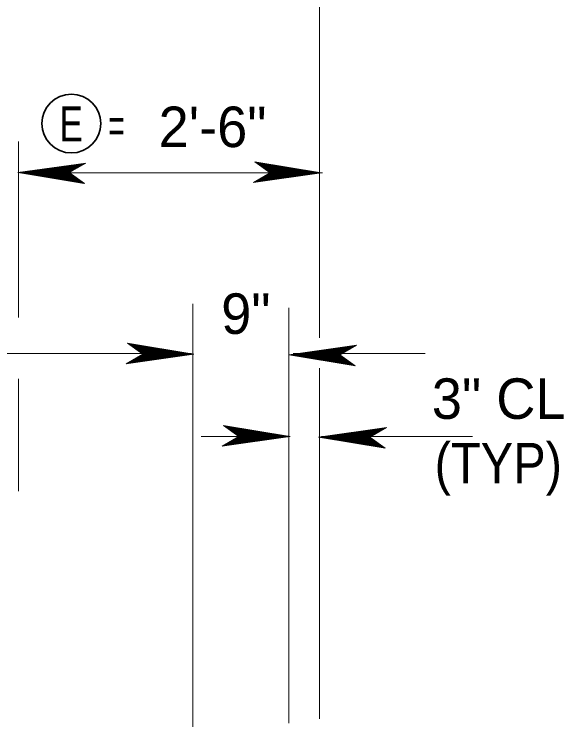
# Model space of a CAD drawing. Extents: x 144 to 252, y 360 to 425.
# Drawn here: x 195.35 to 199.8, y 394.5 to 400.27 of the extents above; entities that cross this region are included whole.
import ezdxf
from ezdxf.enums import TextEntityAlignment as Align

# ---------------------------------------------------------------- set-up
doc = ezdxf.new("R2010")
doc.units = 0
doc.header["$LTSCALE"] = 0.13
for name, color, linetype, lineweight in [('1', 7, 'Continuous', 40), ('16', 7, 'Continuous', 13), ('3', 7, 'Continuous', 13)]:
    doc.layers.add(name, color=color, linetype=linetype, lineweight=lineweight)

msp = doc.modelspace()

# ---------------------------------------------------------------- linework, layer by layer
at = {"layer": '1', "lineweight": 35}
msp.add_circle((195.8129, 399.3848), 0.238, dxfattribs=at)
at = {"layer": '3'}
for p, q in [((197.8208, 397.6492), (197.8208, 401.0623)), ((197.8208, 397.7177), (197.8208, 400.0347)), ((195.3853, 397.8149), (195.3853, 399.2386)), ((195.9291, 399.065), (195.3803, 398.9872)), ((195.9231, 399.0615), (195.3947, 398.9866)), ((195.9196, 399.0595), (195.4056, 398.9866)), ((195.7955, 398.9871), (195.9291, 399.065)), ((197.8364, 398.9853), (197.2987, 399.0746)), ((197.2987, 399.0746), (197.4212, 398.9855)), ((197.822, 398.986), (197.302, 399.0722)), ((197.8112, 398.986), (197.3053, 399.0699)), ((197.7968, 398.986), (197.3095, 399.0668)), ((197.784, 398.986), (197.3132, 399.0641)), ((197.7727, 398.986), (197.3166, 399.0617)), ((197.7583, 398.986), (197.3208, 399.0585)), ((195.915, 399.0568), (195.42, 398.9866)), ((195.9109, 399.0544), (195.4327, 398.9866)), ((195.9109, 399.0544), (195.4327, 398.9866)), ((195.9073, 399.0523), (195.4441, 398.9866)), ((195.9027, 399.0496), (195.4585, 398.9866)), ((195.8986, 399.0472), (195.4712, 398.9866)), ((195.8942, 399.0447), (195.485, 398.9866)), ((195.8897, 399.0421), (195.4988, 398.9866)), ((195.8855, 399.0396), (195.5121, 398.9866)), ((195.881, 399.0369), (195.526, 398.9866)), ((195.877, 399.0347), (195.5386, 398.9866)), ((195.8732, 399.0324), (195.55, 398.9866)), ((195.8682, 399.0296), (195.5657, 398.9866)), ((195.8638, 399.0269), (195.5795, 398.9866)), ((195.8567, 399.0227), (195.5975, 398.9861)), ((195.8598, 399.0247), (195.5991, 398.9877)), ((195.8522, 399.0202), (195.6114, 398.9861)), ((195.848, 399.0177), (195.6246, 398.9861)), ((195.8465, 399.0168), (195.6337, 398.9866)), ((195.8426, 399.0146), (195.6457, 398.9866)), ((195.8382, 399.0119), (195.6595, 398.9866)), ((195.8332, 399.0091), (195.6752, 398.9866)), ((195.8291, 399.0067), (195.6877, 398.9866)), ((195.8248, 399.0042), (195.701, 398.9866)), ((195.821, 399.0019), (195.713, 398.9866)), ((197.7455, 398.986), (197.3246, 399.0557)), ((197.7318, 398.986), (197.3287, 399.0528)), ((197.7179, 398.986), (197.3328, 399.0498)), ((197.7047, 398.986), (197.3367, 399.047)), ((197.6907, 398.986), (197.3407, 399.044)), ((197.6782, 398.986), (197.3445, 399.0413)), ((197.6668, 398.986), (197.3479, 399.0388)), ((197.6511, 398.986), (197.3525, 399.0355)), ((197.6372, 398.986), (197.3566, 399.0325)), ((197.6192, 398.9865), (197.3608, 399.0294)), ((197.6053, 398.9865), (197.365, 399.0264)), ((197.5922, 398.9865), (197.3688, 399.0236)), ((197.5831, 398.986), (197.3726, 399.0208)), ((197.5711, 398.986), (197.3762, 399.0182)), ((197.5572, 398.986), (197.3802, 399.0152)), ((197.5416, 398.986), (197.3849, 399.012)), ((197.529, 398.986), (197.3886, 399.0093)), ((197.5157, 398.986), (197.3925, 399.0064)), ((197.5037, 398.986), (197.3961, 399.0037)), ((197.4892, 398.986), (197.4003, 399.0007)), ((195.3803, 398.9872), (195.918, 398.898)), ((195.7957, 398.9872), (195.3803, 398.9872)), ((195.3947, 398.9866), (195.9147, 398.9003)), ((195.4056, 398.9866), (195.9115, 398.9027)), ((197.8445, 398.9853), (195.4169, 398.9853)), ((195.42, 398.9866), (195.9073, 398.9058)), ((195.4327, 398.9866), (195.9035, 398.9085)), ((195.4441, 398.9866), (195.9002, 398.9109)), ((195.4585, 398.9866), (195.8959, 398.9141)), ((195.4712, 398.9866), (195.8922, 398.9168)), ((195.485, 398.9866), (195.8881, 398.9197)), ((195.4988, 398.9866), (195.884, 398.9228)), ((195.5121, 398.9866), (195.8801, 398.9256)), ((195.526, 398.9866), (195.876, 398.9286)), ((195.5386, 398.9866), (195.8722, 398.9312)), ((195.55, 398.9866), (195.8688, 398.9337)), ((195.5657, 398.9866), (195.8642, 398.9371)), ((195.5795, 398.9866), (195.8602, 398.9401)), ((195.5975, 398.9861), (195.8559, 398.9432)), ((195.6114, 398.9861), (195.8517, 398.9462)), ((195.6246, 398.9861), (195.8479, 398.949)), ((195.6337, 398.9866), (195.8442, 398.9518)), ((195.6457, 398.9866), (195.8406, 398.9543)), ((195.6595, 398.9866), (195.8365, 398.9573)), ((195.6752, 398.9866), (195.8318, 398.9606)), ((195.6877, 398.9866), (195.8282, 398.9633)), ((195.701, 398.9866), (195.8243, 398.9662)), ((195.713, 398.9866), (195.8207, 398.9688)), ((195.8163, 398.9992), (195.7275, 398.9866)), ((195.7275, 398.9866), (195.8164, 398.9718)), ((195.8119, 398.9967), (195.7413, 398.9866)), ((195.7413, 398.9866), (195.8123, 398.9748)), ((195.8078, 398.9943), (195.754, 398.9866)), ((195.754, 398.9866), (195.8086, 398.9776)), ((195.7672, 398.9866), (195.8047, 398.9804)), ((195.8026, 398.9912), (195.7775, 398.9877)), ((195.7999, 398.9897), (195.7787, 398.9866)), ((195.7787, 398.9866), (195.8012, 398.9828)), ((195.7888, 398.9866), (195.7982, 398.9851)), ((195.918, 398.898), (195.7955, 398.9871)), ((197.4212, 398.9855), (197.2877, 398.9076)), ((197.2877, 398.9076), (197.8364, 398.9853)), ((197.2937, 398.9111), (197.822, 398.986)), ((197.2972, 398.9131), (197.8112, 398.986)), ((197.3017, 398.9158), (197.7968, 398.986)), ((197.3058, 398.9182), (197.784, 398.986)), ((197.3058, 398.9182), (197.784, 398.986)), ((197.3095, 398.9203), (197.7727, 398.986)), ((197.3141, 398.923), (197.7583, 398.986)), ((197.3182, 398.9254), (197.7455, 398.986)), ((197.3226, 398.9279), (197.7318, 398.986)), ((197.327, 398.9305), (197.7179, 398.986)), ((197.3312, 398.933), (197.7047, 398.986)), ((197.3357, 398.9357), (197.6907, 398.986)), ((197.3397, 398.9379), (197.6782, 398.986)), ((197.3435, 398.9402), (197.6668, 398.986)), ((197.3485, 398.943), (197.6511, 398.986)), ((197.3529, 398.9457), (197.6372, 398.986)), ((197.3569, 398.9479), (197.6177, 398.9849)), ((197.3601, 398.9498), (197.6192, 398.9865)), ((197.3645, 398.9524), (197.6053, 398.9865)), ((197.3688, 398.9549), (197.5922, 398.9865)), ((197.3702, 398.9557), (197.5831, 398.986)), ((197.3742, 398.958), (197.5711, 398.986)), ((197.3786, 398.9607), (197.5572, 398.986)), ((197.3836, 398.9635), (197.5416, 398.986)), ((197.3877, 398.9659), (197.529, 398.986)), ((197.3919, 398.9684), (197.5157, 398.986)), ((197.3957, 398.9707), (197.5037, 398.986)), ((197.4004, 398.9733), (197.4892, 398.986)), ((197.4754, 398.986), (197.4045, 398.9977)), ((197.4048, 398.9759), (197.4754, 398.986)), ((197.4627, 398.986), (197.4082, 398.995)), ((197.4089, 398.9783), (197.4627, 398.986)), ((197.4495, 398.986), (197.4121, 398.9922)), ((197.4142, 398.9813), (197.4392, 398.9849)), ((197.4381, 398.986), (197.4155, 398.9898)), ((197.4168, 398.9829), (197.4381, 398.986)), ((197.4279, 398.986), (197.4185, 398.9875)), ((197.421, 398.9853), (197.8364, 398.9853)), ((196.7952, 394.4992), (196.7952, 397.9255)), ((197.5733, 394.5272), (197.5733, 397.8934)), ((196.8055, 397.5167), (196.2678, 397.6059)), ((196.2678, 397.6059), (196.3903, 397.5168)), ((196.7911, 397.5173), (196.2711, 397.6036)), ((196.7802, 397.5173), (196.2743, 397.6012)), ((196.7658, 397.5173), (196.2786, 397.5981)), ((196.7531, 397.5173), (196.2823, 397.5954)), ((196.7417, 397.5173), (196.2857, 397.593)), ((196.7273, 397.5173), (196.2899, 397.5898)), ((196.7146, 397.5173), (196.2937, 397.5871)), ((196.7008, 397.5173), (196.2977, 397.5842)), ((196.687, 397.5173), (196.3018, 397.5812)), ((196.6737, 397.5173), (196.3057, 397.5783)), ((196.6598, 397.5173), (196.3098, 397.5753)), ((196.6472, 397.5173), (196.3136, 397.5727)), ((196.6358, 397.5173), (196.317, 397.5702)), ((196.6202, 397.5173), (196.3216, 397.5668)), ((196.6063, 397.5173), (196.3257, 397.5638)), ((196.5883, 397.5178), (196.3299, 397.5607)), ((196.5744, 397.5178), (196.3341, 397.5577)), ((198.1208, 397.5888), (197.5721, 397.511)), ((198.1148, 397.5852), (197.5865, 397.5103)), ((198.1113, 397.5832), (197.5973, 397.5103)), ((198.1068, 397.5806), (197.6118, 397.5103)), ((198.1027, 397.5782), (197.6245, 397.5103)), ((198.1027, 397.5782), (197.6245, 397.5103)), ((198.099, 397.576), (197.6358, 397.5103)), ((198.0944, 397.5733), (197.6502, 397.5103)), ((198.0903, 397.5709), (197.663, 397.5103)), ((198.0859, 397.5684), (197.6767, 397.5103)), ((198.0815, 397.5658), (197.6906, 397.5103)), ((198.0772, 397.5633), (197.7038, 397.5103)), ((198.0727, 397.5607), (197.7177, 397.5103)), ((198.0687, 397.5584), (197.7303, 397.5103)), ((197.9872, 397.5108), (198.1208, 397.5888)), ((190.8138, 397.5218), (196.7735, 397.5218)), ((190.8303, 397.5218), (196.7835, 397.5218)), ((196.3903, 397.5168), (196.2567, 397.4389)), ((196.2567, 397.4389), (196.8055, 397.5167)), ((196.2627, 397.4424), (196.7911, 397.5173)), ((196.2662, 397.4444), (196.7802, 397.5173)), ((196.2708, 397.4471), (196.7658, 397.5173)), ((196.2749, 397.4495), (196.7531, 397.5173)), ((196.2749, 397.4495), (196.7531, 397.5173)), ((196.2786, 397.4517), (196.7417, 397.5173)), ((196.2832, 397.4543), (196.7273, 397.5173)), ((196.2873, 397.4567), (196.7146, 397.5173)), ((196.2917, 397.4592), (196.7008, 397.5173)), ((196.2961, 397.4618), (196.687, 397.5173)), ((196.3003, 397.4643), (196.6737, 397.5173)), ((196.3048, 397.467), (196.6598, 397.5173)), ((196.3088, 397.4692), (196.6472, 397.5173)), ((196.3126, 397.4715), (196.6358, 397.5173)), ((196.3176, 397.4743), (196.6202, 397.5173)), ((196.322, 397.477), (196.6063, 397.5173)), ((196.326, 397.4792), (196.5867, 397.5163)), ((196.3292, 397.4812), (196.5883, 397.5178)), ((196.3336, 397.4837), (196.5744, 397.5178)), ((196.3378, 397.4862), (196.5613, 397.5178)), ((196.5613, 397.5178), (196.3379, 397.5549)), ((196.3393, 397.4871), (196.5522, 397.5173)), ((196.5522, 397.5173), (196.3417, 397.5522)), ((196.3432, 397.4893), (196.5402, 397.5173)), ((196.5402, 397.5173), (196.3452, 397.5496)), ((196.3477, 397.492), (196.5263, 397.5173)), ((196.5263, 397.5173), (196.3493, 397.5466)), ((196.3527, 397.4948), (196.5107, 397.5173)), ((196.5107, 397.5173), (196.354, 397.5433)), ((196.3568, 397.4973), (196.4981, 397.5173)), ((196.4981, 397.5173), (196.3577, 397.5406)), ((196.361, 397.4998), (196.4848, 397.5173)), ((196.4848, 397.5173), (196.3616, 397.5377)), ((196.3648, 397.502), (196.4728, 397.5173)), ((196.4728, 397.5173), (196.3652, 397.5351)), ((196.4583, 397.5173), (196.3694, 397.5321)), ((196.3695, 397.5047), (196.4583, 397.5173)), ((196.4445, 397.5173), (196.3736, 397.5291)), ((196.3739, 397.5072), (196.4445, 397.5173)), ((196.4318, 397.5173), (196.3773, 397.5263)), ((196.378, 397.5096), (196.4318, 397.5173)), ((196.4186, 397.5173), (196.3812, 397.5235)), ((196.3833, 397.5127), (196.4083, 397.5163)), ((196.4072, 397.5173), (196.3846, 397.5211)), ((196.3859, 397.5143), (196.4072, 397.5173)), ((196.397, 397.5173), (196.3876, 397.5188)), ((196.3901, 397.5167), (196.8055, 397.5167)), ((197.5721, 397.511), (198.1097, 397.4217)), ((197.9875, 397.511), (197.5721, 397.511)), ((197.5865, 397.5103), (198.1065, 397.4241)), ((197.5973, 397.5103), (198.1033, 397.4264)), ((197.6077, 397.5218), (198.6776, 397.5218)), ((197.6118, 397.5103), (198.099, 397.4296)), ((197.6245, 397.5103), (198.0952, 397.4323)), ((197.6358, 397.5103), (198.0919, 397.4347)), ((197.6502, 397.5103), (198.0877, 397.4378)), ((197.663, 397.5103), (198.0839, 397.4406)), ((197.6767, 397.5103), (198.0798, 397.4435)), ((197.6906, 397.5103), (198.0757, 397.4465)), ((197.7038, 397.5103), (198.0718, 397.4493)), ((197.7177, 397.5103), (198.0677, 397.4523)), ((197.7303, 397.5103), (198.064, 397.455)), ((198.065, 397.5562), (197.7417, 397.5103)), ((197.7417, 397.5103), (198.0606, 397.4575)), ((198.06, 397.5533), (197.7574, 397.5103)), ((197.7574, 397.5103), (198.056, 397.4608)), ((198.0556, 397.5507), (197.7712, 397.5103)), ((197.7712, 397.5103), (198.0519, 397.4638)), ((198.0484, 397.5465), (197.7892, 397.5098)), ((197.7892, 397.5098), (198.0477, 397.4669)), ((198.0516, 397.5484), (197.7908, 397.5114)), ((198.044, 397.5439), (197.8032, 397.5098)), ((197.8032, 397.5098), (198.0435, 397.4699)), ((198.0397, 397.5414), (197.8163, 397.5098)), ((197.8163, 397.5098), (198.0397, 397.4727)), ((198.0383, 397.5406), (197.8254, 397.5103)), ((197.8254, 397.5103), (198.0359, 397.4755)), ((198.0343, 397.5383), (197.8374, 397.5103)), ((197.8374, 397.5103), (198.0323, 397.4781)), ((198.0299, 397.5357), (197.8512, 397.5103)), ((197.8512, 397.5103), (198.0282, 397.4811)), ((198.0249, 397.5328), (197.8669, 397.5103)), ((197.8669, 397.5103), (198.0236, 397.4843)), ((198.0208, 397.5304), (197.8795, 397.5103)), ((197.8795, 397.5103), (198.0199, 397.4871)), ((198.0166, 397.5279), (197.8928, 397.5103)), ((197.8928, 397.5103), (198.016, 397.4899)), ((198.0127, 397.5257), (197.9048, 397.5103)), ((197.9048, 397.5103), (198.0124, 397.4926)), ((198.0081, 397.523), (197.9193, 397.5103)), ((197.9193, 397.5103), (198.0082, 397.4956)), ((198.0037, 397.5204), (197.9331, 397.5103)), ((197.9331, 397.5103), (198.004, 397.4986)), ((197.9996, 397.5181), (197.9458, 397.5103)), ((197.9458, 397.5103), (198.0003, 397.5013)), ((197.959, 397.5103), (197.9964, 397.5042)), ((197.9943, 397.515), (197.9692, 397.5114)), ((197.9917, 397.5134), (197.9704, 397.5103)), ((197.9704, 397.5103), (197.993, 397.5066)), ((197.9806, 397.5103), (197.99, 397.5088)), ((198.1097, 397.4217), (197.9872, 397.5108)), ((197.8208, 394.5644), (197.8208, 397.4025)), ((195.3853, 396.4067), (195.3853, 397.3173)), ((197.8208, 394.7782), (197.8208, 397.3066)), ((197.5832, 396.8504), (197.0456, 396.9397)), ((197.0456, 396.9397), (197.1681, 396.8506)), ((197.5688, 396.8511), (197.0488, 396.9373)), ((197.558, 396.8511), (197.0521, 396.935)), ((197.5436, 396.8511), (197.0563, 396.9318)), ((197.5308, 396.8511), (197.0601, 396.9292)), ((197.5195, 396.8511), (197.0634, 396.9267)), ((197.5051, 396.8511), (197.0677, 396.9236)), ((198.3632, 396.923), (197.8145, 396.8452)), ((198.2297, 396.8451), (198.3632, 396.923)), ((197.4923, 396.8511), (197.0714, 396.9208)), ((197.4786, 396.8511), (197.0755, 396.9179)), ((197.4647, 396.8511), (197.0796, 396.9149)), ((197.4515, 396.8511), (197.0835, 396.9121)), ((197.4376, 396.8511), (197.0876, 396.9091)), ((197.425, 396.8511), (197.0913, 396.9064)), ((197.4136, 396.8511), (197.0948, 396.9039)), ((197.3979, 396.8511), (197.0993, 396.9006)), ((197.3841, 396.8511), (197.1034, 396.8976)), ((197.3661, 396.8516), (197.1077, 396.8945)), ((197.3522, 396.8516), (197.1118, 396.8915)), ((197.339, 396.8516), (197.1157, 396.8887)), ((197.3299, 396.8511), (197.1194, 396.8859)), ((197.3179, 396.8511), (197.123, 396.8833)), ((197.3041, 396.8511), (197.1271, 396.8803)), ((197.2884, 396.8511), (197.1317, 396.8771)), ((197.2758, 396.8511), (197.1354, 396.8743)), ((197.2626, 396.8511), (197.1393, 396.8715)), ((197.2506, 396.8511), (197.1429, 396.8688)), ((197.2361, 396.8511), (197.1472, 396.8658)), ((198.3572, 396.9195), (197.8289, 396.8446)), ((198.3537, 396.9175), (197.8397, 396.8446)), ((198.3492, 396.9148), (197.8542, 396.8446)), ((198.3451, 396.9124), (197.8669, 396.8446)), ((198.3451, 396.9124), (197.8669, 396.8446)), ((198.3414, 396.9102), (197.8782, 396.8446)), ((198.3368, 396.9076), (197.8927, 396.8446)), ((198.3328, 396.9052), (197.9054, 396.8446)), ((198.3283, 396.9027), (197.9192, 396.8446)), ((198.3239, 396.9001), (197.933, 396.8446)), ((198.3197, 396.8976), (197.9462, 396.8446)), ((198.3152, 396.8949), (197.9602, 396.8446)), ((198.3112, 396.8927), (197.9727, 396.8446)), ((198.3074, 396.8904), (197.9842, 396.8446)), ((198.3024, 396.8876), (197.9998, 396.8446)), ((198.298, 396.8849), (198.0137, 396.8446)), ((198.2908, 396.8807), (198.0317, 396.8441)), ((198.294, 396.8827), (198.0332, 396.8457)), ((198.2864, 396.8782), (198.0456, 396.8441)), ((198.2822, 396.8757), (198.0588, 396.8441)), ((198.2807, 396.8748), (198.0678, 396.8446)), ((198.2767, 396.8726), (198.0798, 396.8446)), ((198.2723, 396.8699), (198.0937, 396.8446)), ((198.2673, 396.8671), (198.1093, 396.8446)), ((198.2632, 396.8647), (198.1219, 396.8446)), ((196.8647, 396.8505), (197.5674, 396.8505)), ((197.1681, 396.8506), (197.0345, 396.7727)), ((197.0345, 396.7727), (197.5832, 396.8504)), ((197.0405, 396.7762), (197.5688, 396.8511)), ((197.044, 396.7782), (197.558, 396.8511)), ((197.0486, 396.7808), (197.5436, 396.8511)), ((197.0527, 396.7833), (197.5308, 396.8511)), ((197.0527, 396.7833), (197.5308, 396.8511)), ((197.0563, 396.7854), (197.5195, 396.8511)), ((197.0609, 396.7881), (197.5051, 396.8511)), ((197.065, 396.7905), (197.4923, 396.8511)), ((197.0694, 396.793), (197.4786, 396.8511)), ((197.0738, 396.7956), (197.4647, 396.8511)), ((197.0781, 396.7981), (197.4515, 396.8511)), ((197.0826, 396.8007), (197.4376, 396.8511)), ((197.0866, 396.803), (197.425, 396.8511)), ((197.0903, 396.8053), (197.4136, 396.8511)), ((197.0953, 396.8081), (197.3979, 396.8511)), ((197.0998, 396.8107), (197.3841, 396.8511)), ((197.1037, 396.813), (197.3645, 396.85)), ((197.1069, 396.8149), (197.3661, 396.8516)), ((197.1113, 396.8175), (197.3522, 396.8516)), ((197.1156, 396.82), (197.339, 396.8516)), ((197.1171, 396.8208), (197.3299, 396.8511)), ((197.121, 396.8231), (197.3179, 396.8511)), ((197.1254, 396.8257), (197.3041, 396.8511)), ((197.1304, 396.8286), (197.2884, 396.8511)), ((197.1345, 396.831), (197.2758, 396.8511)), ((197.1387, 396.8335), (197.2626, 396.8511)), ((197.1426, 396.8357), (197.2506, 396.8511)), ((197.1472, 396.8384), (197.2361, 396.8511)), ((197.2223, 396.8511), (197.1513, 396.8628)), ((197.1517, 396.841), (197.2223, 396.8511)), ((197.2096, 396.8511), (197.155, 396.8601)), ((197.1557, 396.8433), (197.2096, 396.8511)), ((197.1963, 396.8511), (197.1589, 396.8572)), ((197.161, 396.8464), (197.1861, 396.85)), ((197.1849, 396.8511), (197.1623, 396.8548)), ((197.1637, 396.848), (197.1849, 396.8511)), ((197.1747, 396.8511), (197.1653, 396.8526)), ((197.1678, 396.8504), (197.5832, 396.8504)), ((197.8145, 396.8452), (198.3522, 396.756)), ((198.2299, 396.8452), (197.8145, 396.8452)), ((197.8289, 396.8446), (198.3489, 396.7583)), ((197.8388, 396.8505), (199.0601, 396.8505)), ((197.8397, 396.8446), (198.3457, 396.7607)), ((197.8542, 396.8446), (198.3414, 396.7638)), ((197.8669, 396.8446), (198.3377, 396.7665)), ((197.8782, 396.8446), (198.3343, 396.7689)), ((197.8927, 396.8446), (198.3301, 396.7721)), ((197.9054, 396.8446), (198.3263, 396.7748)), ((197.9192, 396.8446), (198.3222, 396.7777)), ((197.933, 396.8446), (198.3182, 396.7808)), ((197.9462, 396.8446), (198.3142, 396.7836)), ((197.9602, 396.8446), (198.3102, 396.7866)), ((197.9727, 396.8446), (198.3064, 396.7892)), ((197.9842, 396.8446), (198.303, 396.7917)), ((197.9998, 396.8446), (198.2984, 396.7951)), ((198.0137, 396.8446), (198.2943, 396.7981)), ((198.0317, 396.8441), (198.2901, 396.8012)), ((198.0456, 396.8441), (198.2859, 396.8042)), ((198.0588, 396.8441), (198.2821, 396.807)), ((198.0678, 396.8446), (198.2783, 396.8098)), ((198.0798, 396.8446), (198.2747, 396.8123)), ((198.0937, 396.8446), (198.2707, 396.8153)), ((198.1093, 396.8446), (198.266, 396.8186)), ((198.1219, 396.8446), (198.2623, 396.8213)), ((198.259, 396.8622), (198.1352, 396.8446)), ((198.1352, 396.8446), (198.2584, 396.8242)), ((198.2552, 396.8599), (198.1472, 396.8446)), ((198.1472, 396.8446), (198.2548, 396.8268)), ((198.2505, 396.8572), (198.1617, 396.8446)), ((198.1617, 396.8446), (198.2506, 396.8298)), ((198.2461, 396.8547), (198.1755, 396.8446)), ((198.1755, 396.8446), (198.2464, 396.8328)), ((198.242, 396.8523), (198.1882, 396.8446)), ((198.1882, 396.8446), (198.2428, 396.8356)), ((198.2014, 396.8446), (198.2388, 396.8384)), ((198.2368, 396.8492), (198.2117, 396.8457)), ((198.2341, 396.8477), (198.2128, 396.8446)), ((198.2128, 396.8446), (198.2354, 396.8408)), ((198.223, 396.8446), (198.2324, 396.8431)), ((198.3522, 396.756), (198.2297, 396.8451)), ((197.8208, 394.7782), (197.8208, 395.361))]:
    msp.add_line(p, q, dxfattribs=at)

# ---------------------------------------------------------------- texts
at = {"layer": '1'}
for s, width, p in [('E', 0.75, (195.8104, 399.2404)), ('=', 0.6, (196.1784, 399.2275))]:
    msp.add_text(s, height=0.2833, dxfattribs=dict(at, width=width)).set_placement(p, align=Align.CENTER)
at = {"layer": '16'}
msp.add_text('2\'-6"', height=0.3281, dxfattribs=at).set_placement((196.9559, 399.194), align=Align.CENTER)
for s, p in [('9"', (197.0256, 397.6812)), ('3" CL', (198.7307, 396.9928))]:
    msp.add_text(s, height=0.3281, dxfattribs=at).set_placement(p)
at = {"layer": '16', "width": 0.9}
msp.add_text('(TYP)', height=0.3281, dxfattribs=at).set_placement((198.7534, 396.4697))

doc.saveas('drawing.dxf')
